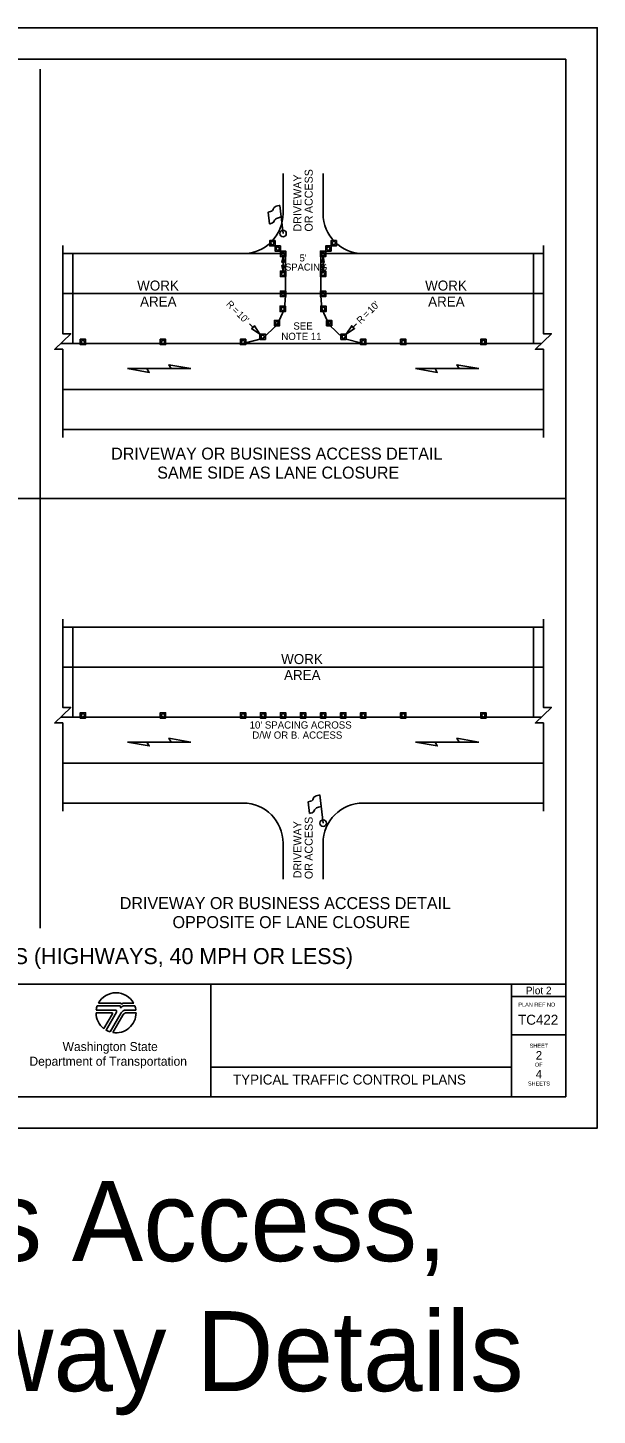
# Model space of a CAD drawing. Extents: x 99999.1 to 100095.7, y 99995 to 100010.7.
# Drawn here: x 100030.38 to 100036.06, y 99996.82 to 100010.69 of the extents above; entities that cross this region are included whole.
import ezdxf

# ---------------------------------------------------------------- set-up
doc = ezdxf.new("R2010")
doc.units = 0
for name, color, linetype in [('RD_ED_DrivewayEdge', 7, 'Continuous'), ('RD_ED_ShoulderPavedEdge', 7, 'Continuous'), ('RD_MK_LineEdgeWhite', 7, 'Continuous'), ('RD_MK_LineSkipCenter', 7, 'Continuous'), ('SH_DE_DetailHeading1Text', 7, 'Continuous'), ('SH_DE_DetailHeading2Text', 7, 'Continuous'), ('SH_GI_PlotLimits', 7, 'Continuous'), ('SH_GI_SheetBorder', 7, 'Continuous'), ('SH_GI_SheetLocationText', 7, 'Continuous'), ('SH_GI_SheetTextInCells', 7, 'Continuous'), ('SH_GI_TitleBlockText', 7, 'Continuous'), ('SH_GI_WSDOTLogo', 7, 'Continuous'), ('TR_WZ_FlaggingStation', 7, 'Continuous'), ('TR_WZ_TrafficCone', 7, 'Continuous'), ('TR_WZ_WorkAreaLabel', 7, 'Continuous'), ('TR_WZ_WorkZoneDetails', 7, 'Continuous'), ('TR_WZ_WorkZoneTextCurrent', 7, 'Continuous')]:
    doc.layers.add(name, color=color, linetype=linetype)

msp = doc.modelspace()

# ---------------------------------------------------------------- linework, layer by layer
at = {"layer": 'RD_ED_DrivewayEdge'}
for p, q in [((100032.925, 100008.83), (100032.925, 100009.23)), ((100033.325, 100008.83), (100033.325, 100009.23)), ((100032.925, 100002.536), (100032.925, 100002.176)), ((100033.325, 100002.536), (100033.325, 100002.176))]:
    msp.add_line(p, q, dxfattribs=at)
for centre, start, end in [((100032.525, 100008.83), 270, 0), ((100033.725, 100008.83), 180, 270), ((100032.525, 100002.536), 0, 90), ((100033.725, 100002.536), 90, 180)]:
    msp.add_arc(centre, 0.4, start, end, dxfattribs=at)
at = {"layer": 'RD_ED_ShoulderPavedEdge'}
for p, q in [((100030.725, 100008.43), (100032.525, 100008.43)), ((100033.725, 100008.43), (100035.525, 100008.43)), ((100030.725, 100006.67), (100035.525, 100006.67)), ((100030.725, 100004.696), (100035.525, 100004.696)), ((100030.725, 100002.936), (100032.525, 100002.936)), ((100033.725, 100002.936), (100035.525, 100002.936))]:
    msp.add_line(p, q, dxfattribs=at)
at = {"layer": 'RD_MK_LineEdgeWhite'}
for p, q in [((100030.725, 100008.03), (100035.525, 100008.03)), ((100030.725, 100007.07), (100035.525, 100007.07)), ((100030.725, 100004.296), (100035.525, 100004.296)), ((100030.725, 100003.336), (100035.525, 100003.336))]:
    msp.add_line(p, q, dxfattribs=at)
at = {"layer": 'RD_MK_LineSkipCenter'}
for points in [[(100035.504, 100007.53), (100030.704, 100007.53)], [(100035.504, 100003.796), (100030.704, 100003.796)]]:
    msp.add_lwpolyline(points, dxfattribs=at)
at = {"layer": 'SH_GI_PlotLimits'}
msp.add_lwpolyline([(100019.062, 99999.687), (100036.062, 99999.687), (100036.062, 100010.687), (100019.062, 100010.687)], close=True, dxfattribs=at)
at = {"layer": 'SH_GI_SheetBorder'}
for p, q in [((100020, 100010.375), (100035.75, 100010.375)), ((100035.75, 100010.375), (100035.75, 100000)), ((100020, 100001.126), (100035.75, 100001.126)), ((100032.205, 100001.126), (100032.205, 100000)), ((100035.208, 100001.126), (100035.208, 100000)), ((100035.208, 100001.001), (100035.75, 100001.001)), ((100035.208, 100000.618), (100035.75, 100000.618)), ((100032.205, 100000.295), (100035.208, 100000.295)), ((100020, 100000), (100035.75, 100000))]:
    msp.add_line(p, q, dxfattribs=at)
at = {"layer": 'SH_GI_WSDOTLogo'}
for p, q in [((100031.059, 100000.866), (100031.25, 100000.866)), ((100031.289, 100000.909), (100031.07, 100000.909)), ((100031.303, 100000.935), (100031.081, 100000.935)), ((100031.433, 100000.935), (100031.335, 100000.935)), ((100031.445, 100000.909), (100031.343, 100000.909)), ((100031.343, 100000.909), (100031.343, 100000.909)), ((100031.356, 100000.866), (100031.456, 100000.866)), ((100031.057, 100000.84), (100031.215, 100000.84)), ((100031.222, 100000.828), (100031.136, 100000.681)), ((100031.261, 100000.846), (100031.157, 100000.667)), ((100031.199, 100000.649), (100031.309, 100000.839)), ((100031.224, 100000.643), (100031.324, 100000.816)), ((100031.365, 100000.839), (100031.457, 100000.839))]:
    msp.add_line(p, q, dxfattribs=at)
for centre, radius, start, end in [((100031.257, 100000.84), 0.2, 28.4787, 151.532), ((100031.257, 100000.84), 0.2, 159.696, 172.5057), ((100031.25, 100000.853), 0.0131, 329.7683, 90), ((100031.289, 100000.895), 0.0148, 327.8418, 89.9985), ((100031.343, 100000.861), 0.0484, 89.9953, 147.8238), ((100031.303, 100000.926), 0.00903, 329.8742, 90.0033), ((100031.356, 100000.812), 0.0542, 90, 149.9974), ((100031.335, 100000.907), 0.0287, 90.0072, 148.1676), ((100031.257, 100000.84), 0.2, 7.4943, 20.2941), ((100031.257, 100000.84), 0.2, 179.9986, 232.8433), ((100031.215, 100000.832), 0.0082, 329.7436, 90), ((100031.257, 100000.84), 0.2, 260.5455, 359.8086), ((100031.365, 100000.792), 0.0476, 90, 150.0543), ((100031.257, 100000.84), 0.2, 239.7929, 253.0448)]:
    msp.add_arc(centre, radius, start, end, dxfattribs=at)
at = {"layer": 'TR_WZ_FlaggingStation'}
for p, q in [((100032.906, 100008.797), (100032.893, 100008.912)), ((100032.925, 100008.63), (100032.893, 100008.911)), ((100032.775, 100008.844), (100032.788, 100008.727)), ((100032.906, 100008.797), (100032.906, 100008.797)), ((100033.175, 100002.949), (100033.188, 100002.832)), ((100033.325, 100002.736), (100033.293, 100003.017)), ((100033.306, 100002.903), (100033.293, 100003.017)), ((100033.306, 100002.903), (100033.306, 100002.903))]:
    msp.add_line(p, q, dxfattribs=at)
for points in [[(100032.893, 100008.912), (100032.887, 100008.91), (100032.869, 100008.907), (100032.856, 100008.903), (100032.846, 100008.897), (100032.837, 100008.892), (100032.832, 100008.885), (100032.827, 100008.877), (100032.827, 100008.871), (100032.821, 100008.862), (100032.811, 100008.854), (100032.798, 100008.849), (100032.775, 100008.844)], [(100032.788, 100008.727), (100032.796, 100008.728), (100032.814, 100008.733), (100032.83, 100008.743), (100032.836, 100008.754), (100032.84, 100008.764), (100032.849, 100008.775), (100032.86, 100008.781), (100032.878, 100008.788), (100032.906, 100008.797)], [(100033.293, 100003.017), (100033.287, 100003.016), (100033.269, 100003.012), (100033.256, 100003.008), (100033.246, 100003.002), (100033.237, 100002.997), (100033.232, 100002.991), (100033.227, 100002.983), (100033.227, 100002.977), (100033.221, 100002.967), (100033.211, 100002.96), (100033.198, 100002.955), (100033.175, 100002.949)], [(100033.188, 100002.832), (100033.196, 100002.834), (100033.214, 100002.838), (100033.23, 100002.849), (100033.236, 100002.859), (100033.24, 100002.87), (100033.249, 100002.88), (100033.26, 100002.887), (100033.278, 100002.894), (100033.306, 100002.903)]]:
    msp.add_lwpolyline(points, dxfattribs=at)
for centre in [(100032.925, 100008.63), (100033.325, 100002.736)]:
    msp.add_circle(centre, 0.0325, dxfattribs=at)
at = {"layer": 'TR_WZ_TrafficCone'}
for points in [[(100032.845, 100008.56), (100032.845, 100008.507), (100032.792, 100008.507), (100032.792, 100008.56), (100032.845, 100008.56)], [(100032.792, 100008.56), (100032.792, 100008.507), (100032.845, 100008.507), (100032.845, 100008.56), (100032.792, 100008.56)], [(100032.898, 100008.507), (100032.898, 100008.454), (100032.845, 100008.454), (100032.845, 100008.507), (100032.898, 100008.507)], [(100032.845, 100008.507), (100032.845, 100008.454), (100032.898, 100008.454), (100032.898, 100008.507), (100032.845, 100008.507)], [(100033.352, 100008.507), (100033.352, 100008.454), (100033.405, 100008.454), (100033.405, 100008.507), (100033.352, 100008.507)], [(100033.405, 100008.507), (100033.405, 100008.454), (100033.352, 100008.454), (100033.352, 100008.507), (100033.405, 100008.507)], [(100033.405, 100008.56), (100033.405, 100008.507), (100033.458, 100008.507), (100033.458, 100008.56), (100033.405, 100008.56)], [(100033.458, 100008.56), (100033.458, 100008.507), (100033.405, 100008.507), (100033.405, 100008.56), (100033.458, 100008.56)], [(100032.898, 100008.454), (100032.952, 100008.454), (100032.952, 100008.4), (100032.898, 100008.4), (100032.898, 100008.454)], [(100032.898, 100008.4), (100032.952, 100008.4), (100032.952, 100008.454), (100032.898, 100008.454), (100032.898, 100008.4)], [(100033.352, 100008.454), (100033.298, 100008.454), (100033.298, 100008.4), (100033.352, 100008.4), (100033.352, 100008.454)], [(100033.352, 100008.4), (100033.298, 100008.4), (100033.298, 100008.454), (100033.352, 100008.454), (100033.352, 100008.4)], [(100032.898, 100008.254), (100032.952, 100008.254), (100032.952, 100008.2), (100032.898, 100008.2), (100032.898, 100008.254)], [(100032.898, 100008.2), (100032.952, 100008.2), (100032.952, 100008.254), (100032.898, 100008.254), (100032.898, 100008.2)], [(100033.352, 100008.254), (100033.298, 100008.254), (100033.298, 100008.2), (100033.352, 100008.2), (100033.352, 100008.254)], [(100033.352, 100008.2), (100033.298, 100008.2), (100033.298, 100008.254), (100033.352, 100008.254), (100033.352, 100008.2)], [(100032.898, 100008.054), (100032.952, 100008.054), (100032.952, 100008), (100032.898, 100008), (100032.898, 100008.054)], [(100032.898, 100008), (100032.952, 100008), (100032.952, 100008.054), (100032.898, 100008.054), (100032.898, 100008)], [(100033.352, 100008.054), (100033.298, 100008.054), (100033.298, 100008), (100033.352, 100008), (100033.352, 100008.054)], [(100033.352, 100008), (100033.298, 100008), (100033.298, 100008.054), (100033.352, 100008.054), (100033.352, 100008)], [(100032.896, 100007.904), (100032.949, 100007.904), (100032.949, 100007.85), (100032.896, 100007.85), (100032.896, 100007.904)], [(100032.896, 100007.85), (100032.949, 100007.85), (100032.949, 100007.904), (100032.896, 100007.904), (100032.896, 100007.85)], [(100033.354, 100007.904), (100033.301, 100007.904), (100033.301, 100007.85), (100033.354, 100007.85), (100033.354, 100007.904)], [(100033.354, 100007.85), (100033.301, 100007.85), (100033.301, 100007.904), (100033.354, 100007.904), (100033.354, 100007.85)], [(100032.838, 100007.762), (100032.891, 100007.762), (100032.891, 100007.708), (100032.838, 100007.708), (100032.838, 100007.762)], [(100032.838, 100007.708), (100032.891, 100007.708), (100032.891, 100007.762), (100032.838, 100007.762), (100032.838, 100007.708)], [(100033.412, 100007.762), (100033.359, 100007.762), (100033.359, 100007.708), (100033.412, 100007.708), (100033.412, 100007.762)], [(100033.412, 100007.708), (100033.359, 100007.708), (100033.359, 100007.762), (100033.412, 100007.762), (100033.412, 100007.708)], [(100030.899, 100007.574), (100030.952, 100007.574), (100030.952, 100007.52), (100030.899, 100007.52), (100030.899, 100007.574)], [(100030.899, 100007.52), (100030.952, 100007.52), (100030.952, 100007.574), (100030.899, 100007.574), (100030.899, 100007.52)], [(100031.699, 100007.574), (100031.752, 100007.574), (100031.752, 100007.52), (100031.699, 100007.52), (100031.699, 100007.574)], [(100031.699, 100007.52), (100031.752, 100007.52), (100031.752, 100007.574), (100031.699, 100007.574), (100031.699, 100007.52)], [(100032.499, 100007.574), (100032.552, 100007.574), (100032.552, 100007.52), (100032.499, 100007.52), (100032.499, 100007.574)], [(100032.499, 100007.52), (100032.552, 100007.52), (100032.552, 100007.574), (100032.499, 100007.574), (100032.499, 100007.52)], [(100032.694, 100007.625), (100032.748, 100007.625), (100032.748, 100007.571), (100032.694, 100007.571), (100032.694, 100007.625)], [(100032.694, 100007.571), (100032.748, 100007.571), (100032.748, 100007.625), (100032.694, 100007.625), (100032.694, 100007.571)], [(100033.556, 100007.625), (100033.502, 100007.625), (100033.502, 100007.571), (100033.556, 100007.571), (100033.556, 100007.625)], [(100033.556, 100007.571), (100033.502, 100007.571), (100033.502, 100007.625), (100033.556, 100007.625), (100033.556, 100007.571)], [(100033.699, 100007.574), (100033.752, 100007.574), (100033.752, 100007.52), (100033.699, 100007.52), (100033.699, 100007.574)], [(100033.699, 100007.52), (100033.752, 100007.52), (100033.752, 100007.574), (100033.699, 100007.574), (100033.699, 100007.52)], [(100034.099, 100007.574), (100034.152, 100007.574), (100034.152, 100007.52), (100034.099, 100007.52), (100034.099, 100007.574)], [(100034.099, 100007.52), (100034.152, 100007.52), (100034.152, 100007.574), (100034.099, 100007.574), (100034.099, 100007.52)], [(100034.899, 100007.574), (100034.952, 100007.574), (100034.952, 100007.52), (100034.899, 100007.52), (100034.899, 100007.574)], [(100034.899, 100007.52), (100034.952, 100007.52), (100034.952, 100007.574), (100034.899, 100007.574), (100034.899, 100007.52)], [(100030.899, 100003.839), (100030.952, 100003.839), (100030.952, 100003.786), (100030.899, 100003.786), (100030.899, 100003.839)], [(100030.899, 100003.786), (100030.952, 100003.786), (100030.952, 100003.839), (100030.899, 100003.839), (100030.899, 100003.786)], [(100031.699, 100003.839), (100031.752, 100003.839), (100031.752, 100003.786), (100031.699, 100003.786), (100031.699, 100003.839)], [(100031.699, 100003.786), (100031.752, 100003.786), (100031.752, 100003.839), (100031.699, 100003.839), (100031.699, 100003.786)], [(100032.499, 100003.839), (100032.552, 100003.839), (100032.552, 100003.786), (100032.499, 100003.786), (100032.499, 100003.839)], [(100032.499, 100003.786), (100032.552, 100003.786), (100032.552, 100003.839), (100032.499, 100003.839), (100032.499, 100003.786)], [(100032.699, 100003.839), (100032.752, 100003.839), (100032.752, 100003.786), (100032.699, 100003.786), (100032.699, 100003.839)], [(100032.699, 100003.786), (100032.752, 100003.786), (100032.752, 100003.839), (100032.699, 100003.839), (100032.699, 100003.786)], [(100032.899, 100003.839), (100032.952, 100003.839), (100032.952, 100003.786), (100032.899, 100003.786), (100032.899, 100003.839)], [(100032.899, 100003.786), (100032.952, 100003.786), (100032.952, 100003.839), (100032.899, 100003.839), (100032.899, 100003.786)], [(100033.099, 100003.839), (100033.152, 100003.839), (100033.152, 100003.786), (100033.099, 100003.786), (100033.099, 100003.839)], [(100033.099, 100003.786), (100033.152, 100003.786), (100033.152, 100003.839), (100033.099, 100003.839), (100033.099, 100003.786)], [(100033.299, 100003.839), (100033.352, 100003.839), (100033.352, 100003.786), (100033.299, 100003.786), (100033.299, 100003.839)], [(100033.299, 100003.786), (100033.352, 100003.786), (100033.352, 100003.839), (100033.299, 100003.839), (100033.299, 100003.786)], [(100033.499, 100003.839), (100033.552, 100003.839), (100033.552, 100003.786), (100033.499, 100003.786), (100033.499, 100003.839)], [(100033.499, 100003.786), (100033.552, 100003.786), (100033.552, 100003.839), (100033.499, 100003.839), (100033.499, 100003.786)], [(100033.699, 100003.839), (100033.752, 100003.839), (100033.752, 100003.786), (100033.699, 100003.786), (100033.699, 100003.839)], [(100033.699, 100003.786), (100033.752, 100003.786), (100033.752, 100003.839), (100033.699, 100003.839), (100033.699, 100003.786)], [(100034.099, 100003.839), (100034.152, 100003.839), (100034.152, 100003.786), (100034.099, 100003.786), (100034.099, 100003.839)], [(100034.099, 100003.786), (100034.152, 100003.786), (100034.152, 100003.839), (100034.099, 100003.839), (100034.099, 100003.786)], [(100034.899, 100003.839), (100034.952, 100003.839), (100034.952, 100003.786), (100034.899, 100003.786), (100034.899, 100003.839)], [(100034.899, 100003.786), (100034.952, 100003.786), (100034.952, 100003.839), (100034.899, 100003.839), (100034.899, 100003.786)]]:
    msp.add_lwpolyline(points, dxfattribs=at)
for centre in [(100032.818, 100008.534), (100032.872, 100008.48), (100033.378, 100008.48), (100033.432, 100008.534), (100032.925, 100008.427), (100033.325, 100008.427), (100032.925, 100008.227), (100033.325, 100008.227), (100032.925, 100008.027), (100033.325, 100008.027), (100032.922, 100007.877), (100033.328, 100007.877), (100032.865, 100007.735), (100033.385, 100007.735), (100030.926, 100007.547), (100031.726, 100007.547), (100032.526, 100007.547), (100032.721, 100007.598), (100033.529, 100007.598), (100033.726, 100007.547), (100034.126, 100007.547), (100034.926, 100007.547), (100030.926, 100003.813), (100031.726, 100003.813), (100032.526, 100003.813), (100032.726, 100003.813), (100032.926, 100003.813), (100033.126, 100003.813), (100033.326, 100003.813), (100033.526, 100003.813), (100033.726, 100003.813), (100034.126, 100003.813), (100034.926, 100003.813)]:
    msp.add_circle(centre, 0.0167, dxfattribs=at)
at = {"layer": 'TR_WZ_WorkZoneDetails'}
for p, q in [((100030.5, 100010.275), (100030.5, 100001.686)), ((100032.925, 100008.346), (100032.925, 100008.308)), ((100033.325, 100008.346), (100033.325, 100008.308)), ((100032.628, 100007.691), (100032.59, 100007.729)), ((100033.622, 100007.691), (100033.66, 100007.729)), ((100031.566, 100007.28), (100031.808, 100007.28)), ((100031.808, 100007.28), (100031.566, 100007.28)), ((100034.443, 100007.28), (100034.684, 100007.28)), ((100034.684, 100007.28), (100034.443, 100007.28)), ((100030.5, 100005.98), (100025.25, 100005.98)), ((100035.75, 100005.98), (100030.5, 100005.98)), ((100031.566, 100003.546), (100031.808, 100003.546)), ((100031.808, 100003.546), (100031.566, 100003.546)), ((100034.443, 100003.546), (100034.684, 100003.546)), ((100034.684, 100003.546), (100034.443, 100003.546))]:
    msp.add_line(p, q, dxfattribs=at)
for points in [[(100030.725, 100006.59), (100030.725, 100007.473), (100030.645, 100007.473), (100030.805, 100007.628), (100030.725, 100007.628), (100030.725, 100008.51)], [(100035.525, 100006.59), (100035.525, 100007.473), (100035.445, 100007.473), (100035.605, 100007.628), (100035.525, 100007.628), (100035.525, 100008.51)], [(100030.725, 100002.856), (100030.725, 100003.738), (100030.645, 100003.738), (100030.805, 100003.893), (100030.725, 100003.893), (100030.725, 100004.776)], [(100035.525, 100002.856), (100035.525, 100003.738), (100035.445, 100003.738), (100035.605, 100003.893), (100035.525, 100003.893), (100035.525, 100004.776)]]:
    msp.add_lwpolyline(points, dxfattribs=at)
for points in [[(100032.948, 100008.43), (100032.948, 100008.207), (100032.948, 100008.007), (100032.939, 100007.877), (100032.939, 100007.877), (100032.939, 100007.877), (100032.865, 100007.718), (100032.865, 100007.718), (100032.865, 100007.718), (100032.721, 100007.581), (100032.526, 100007.53), (100031.529, 100007.53), (100030.949, 100007.53), (100030.825, 100007.53), (100030.825, 100008.43)], [(100032.925, 100008.4), (100032.936, 100008.343), (100032.925, 100008.346), (100032.914, 100008.343)], [(100035.425, 100008.43), (100035.425, 100008.03), (100035.425, 100007.53), (100034.501, 100007.53), (100034.501, 100007.53), (100034.501, 100007.53), (100033.726, 100007.53), (100033.726, 100007.53), (100033.726, 100007.53), (100033.529, 100007.581), (100033.385, 100007.718), (100033.311, 100007.877), (100033.302, 100008.007), (100033.302, 100008.207), (100033.302, 100008.43)], [(100033.325, 100008.4), (100033.336, 100008.343), (100033.325, 100008.346), (100033.314, 100008.343)], [(100032.925, 100008.254), (100032.936, 100008.311), (100032.925, 100008.308), (100032.914, 100008.311)], [(100033.325, 100008.254), (100033.336, 100008.311), (100033.325, 100008.308), (100033.314, 100008.311)], [(100032.694, 100007.625), (100032.611, 100007.681), (100032.628, 100007.691), (100032.639, 100007.708)], [(100033.556, 100007.625), (100033.639, 100007.681), (100033.622, 100007.691), (100033.611, 100007.708)], [(100031.37, 100007.28), (100031.589, 100007.242), (100031.566, 100007.28)], [(100032.004, 100007.28), (100031.785, 100007.319), (100031.808, 100007.28)], [(100034.247, 100007.28), (100034.465, 100007.242), (100034.443, 100007.28)], [(100034.881, 100007.28), (100034.662, 100007.319), (100034.684, 100007.28)], [(100030.825, 100004.696), (100030.825, 100003.796), (100035.425, 100003.796), (100035.425, 100004.696)], [(100031.37, 100003.546), (100031.589, 100003.507), (100031.566, 100003.546)], [(100032.004, 100003.546), (100031.785, 100003.584), (100031.808, 100003.546)], [(100034.247, 100003.546), (100034.465, 100003.507), (100034.443, 100003.546)], [(100034.881, 100003.546), (100034.662, 100003.584), (100034.684, 100003.546)]]:
    msp.add_lwpolyline(points, close=True, dxfattribs=at)

# ---------------------------------------------------------------- texts
at = {"layer": 'SH_DE_DetailHeading1Text'}
msp.add_text('ALTERNATING 1-LANE, 2-WAY TRAFFIC: FLAGGER-CONTROLLED + TEMP. RUMBLE STRIPS (HIGHWAYS, 40 MPH OR LESS)', height=0.16, rotation=360, dxfattribs=at).set_placement((100020.956, 100001.326))
at = {"layer": 'SH_DE_DetailHeading2Text'}
for s, p in [('DRIVEWAY OR BUSINESS ACCESS DETAIL', (100031.208, 100006.37)), ('SAME SIDE AS LANE CLOSURE', (100031.668, 100006.18)), ('DRIVEWAY OR BUSINESS ACCESS DETAIL', (100031.294, 100001.876)), ('OPPOSITE OF LANE CLOSURE', (100031.821, 100001.686))]:
    msp.add_text(s, height=0.12, rotation=360, dxfattribs=at).set_placement(p)
at = {"layer": 'SH_GI_SheetBorder'}
msp.add_text('PLAN REF NO', height=0.04003, dxfattribs=at).set_placement((100035.275, 100000.901))
at = {"layer": 'SH_GI_SheetLocationText'}
for s, height, p in [('Plot 2', 0.075, (100035.35, 100001.025)), ('Driveway, Business Access,', 0.8, (100021.184, 99998.357)), ('or Intersecting Roadway Details', 0.8, (100020.225, 99997.057))]:
    msp.add_text(s, height=height, dxfattribs=at).set_placement(p)
at = {"layer": 'SH_GI_SheetTextInCells'}
for s, height, p in [('Washington State', 0.09007, (100030.723, 100000.457)), ('SHEET', 0.04, (100035.388, 100000.49)), ('Department of Transportation', 0.09007, (100030.392, 100000.31)), ('OF', 0.04, (100035.441, 100000.301)), ('SHEETS', 0.04, (100035.37, 100000.112))]:
    msp.add_text(s, height=height, dxfattribs=at).set_placement(p)
at = {"layer": 'SH_GI_TitleBlockText'}
for s, height, p in [('TC422', 0.1, (100035.272, 100000.72)), ('2', 0.085, (100035.449, 100000.372)), ('TYPICAL TRAFFIC CONTROL PLANS', 0.1, (100032.425, 100000.122)), ('4', 0.085, (100035.449, 100000.184))]:
    msp.add_text(s, height=height, dxfattribs=at).set_placement(p)
at = {"layer": 'TR_WZ_WorkAreaLabel'}
for s, p in [('WORK', (100031.468, 100008.06)), ('WORK', (100034.344, 100008.06)), ('AREA', (100031.497, 100007.9)), ('AREA', (100034.374, 100007.9)), ('WORK', (100032.906, 100004.326)), ('AREA', (100032.935, 100004.166))]:
    msp.add_text(s, height=0.1, dxfattribs=at).set_placement(p)
at = {"layer": 'TR_WZ_WorkZoneTextCurrent'}
for s, height, rotation, p in [('DRIVEWAY', 0.08, 90, (100033.109, 100008.65)), ('ACCESS', 0.08, 90, (100033.221, 100008.834)), ('OR', 0.08, 90, (100033.221, 100008.65)), ('R', 0.07, 315, (100032.351, 100007.919)), ("10'", 0.07, 45, (100033.808, 100007.827)), ('=', 0.07, 315, (100032.41, 100007.859)), ("10'", 0.07, 315, (100032.457, 100007.813)), ('R', 0.07, 45, (100033.701, 100007.721)), ('=', 0.07, 45, (100033.761, 100007.78)), ('ACCESS', 0.08, 90, (100033.221, 100002.36)), ('DRIVEWAY', 0.08, 90, (100033.109, 100002.184)), ('OR', 0.08, 90, (100033.221, 100002.176))]:
    msp.add_text(s, height=height, rotation=rotation, dxfattribs=at).set_placement(p)
for s, height, p in [("5'", 0.07, (100033.09, 100008.351)), ('SPACING', 0.07, (100032.945, 100008.26)), ('SEE', 0.072, (100033.028, 100007.67)), ('NOTE 11', 0.072, (100032.908, 100007.566)), ("10' SPACING ACROSS", 0.072, (100032.591, 100003.681)), ('D/W OR B. ACCESS', 0.072, (100032.618, 100003.58))]:
    msp.add_text(s, height=height, dxfattribs=at).set_placement(p)

doc.saveas('drawing.dxf')
